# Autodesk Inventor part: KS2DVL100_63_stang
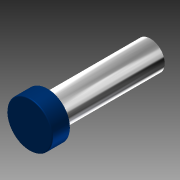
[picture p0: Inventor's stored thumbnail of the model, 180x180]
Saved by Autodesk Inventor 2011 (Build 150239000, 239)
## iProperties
Created: 2010-11
Document SubType Name: Modeling
Designer: TB
Mass: 161.233 g
Surface Area: 236.814 cm^2
Volume: 161.233 cm^3
Density: 1 g/cm^3
Author: TB
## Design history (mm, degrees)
sketch "Sketch2"
  geometry: L1 (-35, -3)-(-35, 3) reference; L2 (-35, -9)-(-35, 9) reference; L3 (-35, 31.5)-(-301, 31.5); L4 (-301, 31.5)-(-301, 0); L5 (-301, 0)-(-35, 0); L6 (-35, 0)-(-35, 31.5); L7 (-301, 31.5)-(-261, 31.5); L8 (-261, 31.5)-(-261, 50); L9 (-261, 50)-(-301, 50); L10 (-301, 50)-(-301, 31.5); 1 further point
  constraints: 16 end point, 4 parallel, 2 horizontal, 2 perpendicular, 1 midpoint
  dimensions: "Dia" = 63 diameter of L3 L5; "d3" = 266 distance of L3.start L3.end (computed from Slaglengde, Forlengelse_rør); "StempelDia" = 100 diameter of L9 L5; "StempelLengde" = 40 distance of L8.end L9.end
revolve "Revolution1" sketch "Sketch2" stored, may be unused: angle "d6" = 90 deg
fillet "Fillet1" dims "d7" = 2
sketch "Sketch3"
  geometry: L1 (-301, -48)-(-301, 48) reference; L2 (-301, 0)-(-301.01, 0); L3 (-301, 0)-(-301, 0.01); A1 r 0.01 centre (-301, 0) between (-301, 0.01) and (-301.01, 0); 1 further point
  constraints: 4 end point, 2 point on circle, 1 centre point, 1 midpoint, 1 perpendicular, 1 point on line
  dimensions: "d8" = 0.01 distance of L2.start L2.end; "d9" = 0.01 distance of L2.start L3.end (= d8); "d10" = 0.01 radius of A1 (= d8)
revolve "Revolution2" sketch "Sketch3" stored, may be unused: angle "d11" = 90 deg
body "Solid1"
node "Projected Loop2"
other parameters: "Forlengelse_rør" = 0
